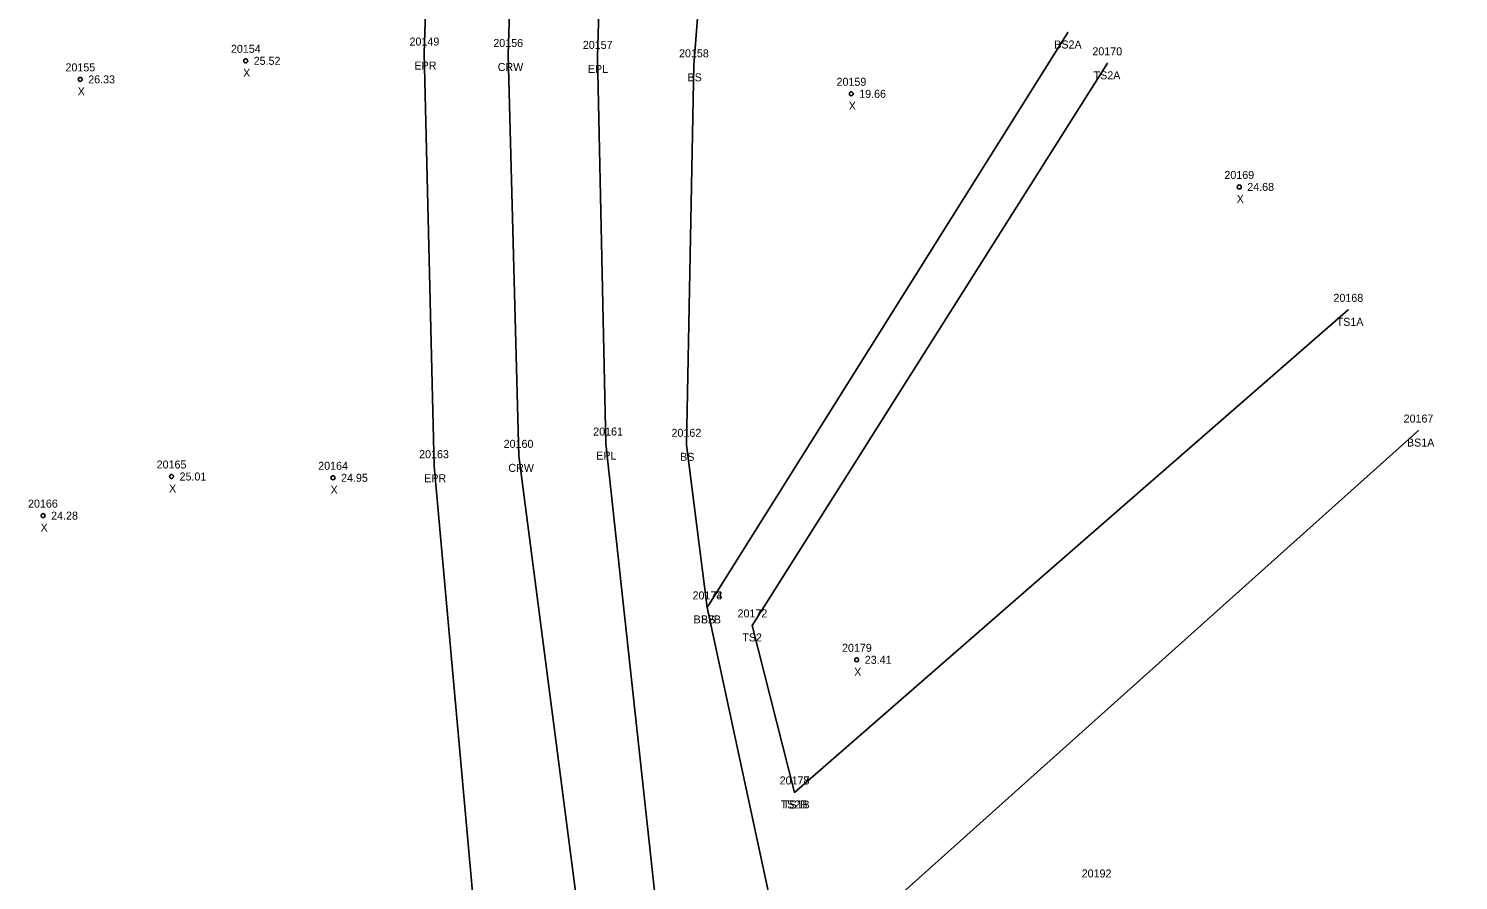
# Model space of a CAD drawing. Extents: x 2432729 to 2433340, y 684958 to 688103.
# Drawn here: x 2432864.4 to 2433043.1, y 687055.8 to 687162.2 of the extents above; entities that cross this region are included whole.
import ezdxf

# ---------------------------------------------------------------- set-up
doc = ezdxf.new("R2010")
doc.units = 0
for name, color, linetype in [('RD_DTM_BkLn1', 7, 'Continuous'), ('RD_DTM_BkLn2', 7, 'Continuous'), ('RD_EX_H2O_txCode', 7, 'Continuous'), ('RD_EX_Road', 7, 'Continuous'), ('RD_EX_Road_txCode', 7, 'Continuous'), ('RD_Sketch8', 7, 'Continuous'), ('RD_SMD_Locator', 7, 'Continuous'), ('RD_SMD_Misc', 7, 'Continuous')]:
    doc.layers.add(name, color=color, linetype=linetype)

msp = doc.modelspace()

# ---------------------------------------------------------------- linework, layer by layer
at = {"layer": 'RD_DTM_BkLn1'}
msp.add_lwpolyline([(2432926.02, 687213.66), (2432924.35, 687158.94), (2432925.68, 687108.84), (2432939.7, 687000.92), (2432956.93, 686927.39), (2432975, 686866.8), (2433007.19, 686769.33), (2433041.66, 686669.67), (2433075.97, 686569.51), (2433108.49, 686474.01), (2433123.82, 686426.48), (2433137.99, 686374.7), (2433148.76, 686320.1), (2433154.8, 686269.16), (2433155.78, 686212.93), (2433152.37, 686164.52), (2433145.67, 686113.9), (2433140.38, 686078.83)], dxfattribs=at)
at = {"layer": 'RD_DTM_BkLn2'}
for p, q in [((2432994.28, 687161.75), (2432949.21, 687089.9)), ((2433029.3, 687127.09), (2432960.1, 687066.77)), ((2433038.07, 687112), (2432959.59, 687041.68))]:
    msp.add_line(p, q, dxfattribs=at)
for points in [[(2432956.03, 687234.5), (2432952.13, 687211.69), (2432949.74, 687186.09), (2432947.53, 687157.65), (2432946.61, 687110.22), (2432949.21, 687089.9), (2432959.59, 687041.68)], [(2432999.21, 687157.9), (2432954.83, 687087.65), (2432960.1, 687066.77)]]:
    msp.add_lwpolyline(points, dxfattribs=at)
at = {"layer": 'RD_EX_Road'}
for points in [[(2432915.64, 687215.4), (2432913.86, 687159.12), (2432915.08, 687107.55), (2432919.97, 687053.4), (2432928.7, 686998.89), (2432946.77, 686924.59), (2432964.57, 686864), (2432997.3, 686766.34), (2433031.44, 686666.38), (2433066.06, 686565.78), (2433098.73, 686469.74), (2433113.88, 686422.91), (2433127.93, 686372.14), (2433139.1, 686314.76), (2433144.47, 686268.02), (2433145.44, 686213), (2433142.32, 686164.92), (2433135.44, 686115.75), (2433128.09, 686081.14)], [(2432937.12, 687213.43), (2432935.51, 687158.7), (2432936.54, 687110.38), (2432944.97, 687033.04), (2432950.24, 687002.26), (2432966.49, 686930.23), (2432984.9, 686870.1), (2433011.7, 686787.41), (2433010.33, 686784.51), (2433011.78, 686772.99), (2433015.37, 686760.79), (2433021.02, 686752.9), (2433031.88, 686728.09), (2433052.76, 686670.56), (2433070.23, 686619.38), (2433072.02, 686607.31)]]:
    msp.add_lwpolyline(points, dxfattribs=at)
at = {"layer": 'RD_SMD_Locator'}
for centre, radius in [((2432994.28, 687161.75), 0.001), ((2432913.86, 687159.12), 0.001), ((2432891.55, 687158.21), 0.25), ((2432924.35, 687158.94), 0.001), ((2432935.51, 687158.7), 0.001), ((2432947.53, 687157.65), 0.001), ((2432999.21, 687157.9), 0.001), ((2432870.88, 687155.89), 0.25), ((2432967.2, 687154.09), 0.25), ((2433015.68, 687142.45), 0.25), ((2433029.3, 687127.09), 0.001), ((2433038.07, 687112), 0.001), ((2432936.54, 687110.38), 0.001), ((2432946.61, 687110.22), 0.001), ((2432915.08, 687107.55), 0.001), ((2432925.68, 687108.84), 0.001), ((2432882.29, 687106.26), 0.25), ((2432902.47, 687106.1), 0.25), ((2432866.25, 687101.37), 0.25), ((2432949.21, 687089.9), 0.001), ((2432949.21, 687089.9), 0.001), ((2432954.83, 687087.65), 0.001), ((2432967.89, 687083.35), 0.25), ((2432960.1, 687066.77), 0.001), ((2432960.1, 687066.77), 0.001)]:
    msp.add_circle(centre, radius, dxfattribs=at)

# ---------------------------------------------------------------- texts
at = {"layer": 'RD_EX_H2O_txCode'}
msp.add_text('20192', height=1, dxfattribs=at).set_placement((2432995.99, 687056.15))
at = {"layer": 'RD_EX_Road_txCode'}
for s, p in [('20149', (2432912.02, 687160.12)), ('20157', (2432933.67, 687159.7)), ('EPR', (2432912.63, 687157.12)), ('EPL', (2432934.3, 687156.7)), ('20161', (2432934.97, 687111.38)), ('20163', (2432913.22, 687108.55)), ('EPL', (2432935.34, 687108.38)), ('EPR', (2432913.85, 687105.55))]:
    msp.add_text(s, height=1, dxfattribs=at).set_placement(p)
at = {"layer": 'RD_Sketch8'}
for s, p in [('20154', (2432889.71, 687159.21)), ('20155', (2432869.04, 687156.89)), ('X', (2432891.23, 687156.21)), ('25.52', (2432892.55, 687157.71)), ('26.33', (2432871.88, 687155.39)), ('20159', (2432965.37, 687155.09)), ('X', (2432870.56, 687153.89)), ('19.66', (2432968.2, 687153.59)), ('X', (2432966.89, 687152.09)), ('20169', (2433013.82, 687143.45)), ('24.68', (2433016.68, 687141.95)), ('X', (2433015.36, 687140.45)), ('20165', (2432880.43, 687107.26)), ('20164', (2432900.61, 687107.1)), ('25.01', (2432883.29, 687105.76)), ('24.95', (2432903.47, 687105.6)), ('X', (2432881.98, 687104.26)), ('X', (2432902.16, 687104.1)), ('20166', (2432864.36, 687102.37)), ('24.28', (2432867.25, 687100.87)), ('X', (2432865.93, 687099.37)), ('20179', (2432966.05, 687084.35)), ('X', (2432967.57, 687081.35)), ('23.41', (2432968.89, 687082.85))]:
    msp.add_text(s, height=1, dxfattribs=at).set_placement(p)
at = {"layer": 'RD_SMD_Misc'}
for s, p in [('20156', (2432922.49, 687159.94)), ('20158', (2432945.69, 687158.65)), ('BS2A', (2432992.57, 687159.75)), ('20170', (2432997.33, 687158.9)), ('CRW', (2432923.04, 687156.94)), ('BS', (2432946.75, 687155.65)), ('TS2A', (2432997.48, 687155.9)), ('20168', (2433027.45, 687128.09)), ('TS1A', (2433027.85, 687125.09)), ('20167', (2433036.21, 687113)), ('20160', (2432923.78, 687109.84)), ('20162', (2432944.75, 687111.22)), ('BS1A', (2433036.63, 687110)), ('BS', (2432945.83, 687108.22)), ('CRW', (2432924.37, 687106.84)), ('20173', (2432947.38, 687090.9)), ('20174', (2432947.38, 687090.9)), ('20172', (2432953, 687088.65)), ('BS2B', (2432947.51, 687087.9)), ('BS', (2432948.43, 687087.9)), ('TS2', (2432953.59, 687085.65)), ('20177', (2432958.26, 687067.77)), ('20178', (2432958.26, 687067.77)), ('TS2B', (2432958.38, 687064.77)), ('TS1B', (2432958.66, 687064.77))]:
    msp.add_text(s, height=1, dxfattribs=at).set_placement(p)

doc.saveas('drawing.dxf')
